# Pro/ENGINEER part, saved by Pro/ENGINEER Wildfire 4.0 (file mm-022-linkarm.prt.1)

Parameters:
  METRIC = "NO"

Other parameters: PITCH, DRILL_DIAMETER, THREAD_DIAMETER, THREADS_PER_INCH, THREAD_DEPTH, THREAD_LENGTH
